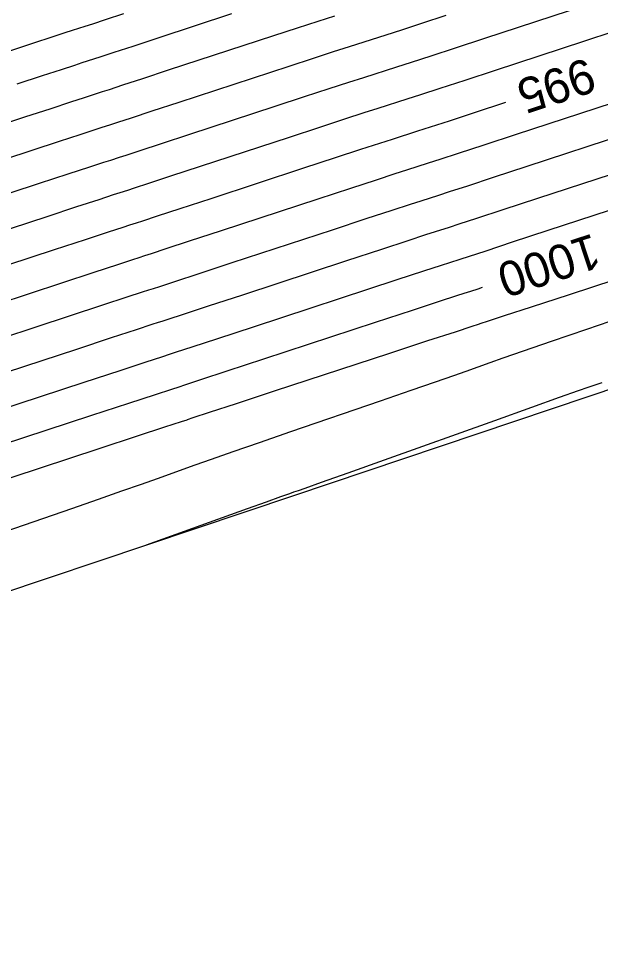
# Model space of a CAD drawing. Extents: x 2175772 to 2185556, y 721391 to 722853.
# Drawn here: x 2178934 to 2178980.9, y 721822.4 to 721896.5 of the extents above; entities that cross this region are included whole.
import ezdxf

# ---------------------------------------------------------------- set-up
doc = ezdxf.new("R2010")
doc.units = 0
for name, color, linetype in [('DT_X_Contour_Major', 7, 'Continuous'), ('DT_X_Contour_Minor', 7, 'Continuous'), ('DT_X_TIN_Hull', 7, 'Continuous')]:
    doc.layers.add(name, color=color, linetype=linetype)

msp = doc.modelspace()

# ---------------------------------------------------------------- linework, layer by layer
at = {"layer": 'DT_X_Contour_Major'}
for points in [[(2178951.175, 721896.819), (2178945.224, 721894.866), (2178943.227, 721894.21), (2178941.699, 721893.71), (2178940.64, 721893.364), (2178940.051, 721893.173), (2178939.106, 721892.87), (2178938.513, 721892.678), (2178937.446, 721892.329), (2178935.904, 721891.824), (2178933.887, 721891.162)], [(2178973.246, 721889.683), (2178970.717, 721888.854), (2178968.69, 721888.191), (2178967.167, 721887.695), (2178966.147, 721887.366), (2178964.099, 721886.711), (2178963.077, 721886.381), (2178961.546, 721885.882), (2178959.507, 721885.215), (2178956.96, 721884.38), (2178949.488, 721881.928), (2178947.011, 721881.115), (2178945.184, 721880.516), (2178944.008, 721880.131), (2178943.482, 721879.96), (2178942.946, 721879.788), (2178942.417, 721879.615), (2178941.229, 721879.227), (2178939.385, 721878.622), (2178936.883, 721877.801), (2178929.334, 721875.323)], [(2178971.364, 721874.761), (2178970.997, 721874.641), (2178970.406, 721874.448), (2178969.882, 721874.281), (2178969.289, 721874.087), (2178967.901, 721873.633), (2178965.72, 721872.918), (2178962.745, 721871.941), (2178953.752, 721868.99), (2178950.795, 721868.019), (2178948.67, 721867.322), (2178947.376, 721866.897), (2178946.913, 721866.746), (2178946.32, 721866.552), (2178945.013, 721866.124), (2178942.866, 721865.419), (2178939.879, 721864.439), (2178930.794, 721861.457)]]:
    msp.add_lwpolyline(points, dxfattribs=at)
at = {"layer": 'DT_X_Contour_Minor'}
for points in [[(2178978.356, 721897.083), (2178971.545, 721894.847), (2178969.186, 721894.074), (2178967.216, 721893.431), (2178965.635, 721892.917), (2178964.444, 721892.533), (2178961.786, 721891.683), (2178960.593, 721891.298), (2178959.005, 721890.782), (2178957.022, 721890.135), (2178954.646, 721889.356), (2178947.782, 721887.103), (2178945.497, 721886.353), (2178943.79, 721885.794), (2178942.661, 721885.424), (2178942.11, 721885.245), (2178941.41, 721885.021), (2178940.855, 721884.84), (2178939.716, 721884.468), (2178937.993, 721883.903), (2178935.684, 721883.145), (2178926.354, 721880.084)], [(2178959.473, 721896.655), (2178958.108, 721896.216), (2178956.463, 721895.682), (2178954.537, 721895.054), (2178946.076, 721892.278), (2178943.984, 721891.591), (2178942.396, 721891.071), (2178941.314, 721890.718), (2178940.737, 721890.531), (2178939.874, 721890.254), (2178939.294, 721890.066), (2178938.203, 721889.709), (2178936.6, 721889.184), (2178934.486, 721888.49), (2178928.166, 721886.416)], [(2178968.42, 721896.684), (2178966.479, 721896.05), (2178964.869, 721895.528), (2178963.592, 721895.117), (2178960.63, 721894.169), (2178959.35, 721893.757), (2178957.734, 721893.232), (2178955.78, 721892.594), (2178946.929, 721889.69), (2178944.74, 721888.972), (2178943.093, 721888.432), (2178941.988, 721888.071), (2178941.424, 721887.888), (2178940.642, 721887.637), (2178940.075, 721887.453), (2178938.96, 721887.088), (2178937.296, 721886.543), (2178935.085, 721885.818), (2178928.458, 721883.642)], [(2178942.47, 721896.83), (2178941.002, 721896.349), (2178939.967, 721896.011), (2178939.365, 721895.816), (2178938.337, 721895.487), (2178937.733, 721895.291), (2178936.69, 721894.95), (2178935.208, 721894.465), (2178933.287, 721893.835)], [(2178981.958, 721895.403), (2178979.511, 721894.6), (2178972.396, 721892.266), (2178969.952, 721891.464), (2178967.953, 721890.811), (2178966.401, 721890.306), (2178965.296, 721889.95), (2178962.943, 721889.197), (2178961.835, 721888.84), (2178960.275, 721888.332), (2178958.265, 721887.675), (2178955.803, 721886.868), (2178948.635, 721884.515), (2178946.254, 721883.734), (2178944.487, 721883.155), (2178943.335, 721882.778), (2178942.796, 721882.602), (2178942.178, 721882.404), (2178941.636, 721882.228), (2178940.473, 721881.847), (2178938.689, 721881.262), (2178936.284, 721880.473), (2178929.042, 721878.096)], [(2178981.821, 721889.636), (2178974.098, 721887.102), (2178971.483, 721886.244), (2178969.428, 721885.572), (2178967.933, 721885.084), (2178966.999, 721884.783), (2178965.256, 721884.225), (2178964.319, 721883.922), (2178962.817, 721883.433), (2178960.75, 721882.756), (2178958.117, 721881.892), (2178950.341, 721879.34), (2178947.768, 721878.496), (2178945.882, 721877.877), (2178944.682, 721877.484), (2178944.168, 721877.317), (2178943.714, 721877.171), (2178943.197, 721877.003), (2178941.986, 721876.606), (2178940.081, 721875.981), (2178937.482, 721875.128), (2178929.626, 721872.55)], [(2178982.976, 721887.154), (2178974.949, 721884.52), (2178972.248, 721883.634), (2178970.165, 721882.952), (2178968.699, 721882.474), (2178967.851, 721882.199), (2178966.412, 721881.739), (2178965.562, 721881.463), (2178964.088, 721880.983), (2178961.992, 721880.296), (2178959.274, 721879.405), (2178951.193, 721876.752), (2178948.525, 721875.877), (2178946.579, 721875.238), (2178945.355, 721874.837), (2178944.854, 721874.674), (2178944.483, 721874.555), (2178943.978, 721874.39), (2178942.743, 721873.985), (2178940.777, 721873.341), (2178938.081, 721872.456), (2178929.918, 721869.776)], [(2178984.13, 721884.672), (2178975.8, 721881.938), (2178973.014, 721881.024), (2178970.902, 721880.332), (2178969.465, 721879.863), (2178968.703, 721879.616), (2178967.569, 721879.253), (2178966.804, 721879.005), (2178965.359, 721878.533), (2178963.235, 721877.837), (2178960.431, 721876.917), (2178952.046, 721874.165), (2178949.282, 721873.258), (2178947.276, 721872.6), (2178946.029, 721872.191), (2178945.541, 721872.031), (2178945.251, 721871.938), (2178944.759, 721871.778), (2178943.499, 721871.365), (2178941.473, 721870.7), (2178938.68, 721869.783), (2178930.21, 721867.003)], [(2178985.285, 721882.189), (2178976.651, 721879.356), (2178973.78, 721878.414), (2178971.639, 721877.712), (2178969.554, 721877.032), (2178968.726, 721876.767), (2178968.046, 721876.546), (2178966.63, 721876.083), (2178964.477, 721875.377), (2178952.899, 721871.577), (2178950.038, 721870.638), (2178947.973, 721869.961), (2178946.702, 721869.544), (2178946.227, 721869.389), (2178945.539, 721869.165), (2178944.256, 721868.744), (2178942.17, 721868.06), (2178939.28, 721867.111), (2178930.502, 721864.23)], [(2178987.595, 721877.225), (2178978.353, 721874.192), (2178975.311, 721873.194), (2178973.114, 721872.473), (2178971.763, 721872.03), (2178971.258, 721871.865), (2178971.039, 721871.795), (2178970.531, 721871.629), (2178969.172, 721871.183), (2178966.962, 721870.458), (2178963.902, 721869.454), (2178954.605, 721866.402), (2178951.552, 721865.4), (2178949.367, 721864.683), (2178948.049, 721864.251), (2178947.599, 721864.103), (2178947.555, 721864.089), (2178947.1, 721863.94), (2178945.769, 721863.503), (2178943.562, 721862.778), (2178940.478, 721861.766), (2178931.086, 721858.683)], [(2178988.204, 721874.275), (2178979.765, 721871.386), (2178976.905, 721870.406), (2178974.654, 721869.631), (2178973.01, 721869.061), (2178971.976, 721868.698), (2178970.027, 721868.002), (2178969.049, 721867.657), (2178967.575, 721867.143), (2178965.606, 721866.462), (2178963.141, 721865.612), (2178955.907, 721863.123), (2178953.391, 721862.255), (2178951.268, 721861.518), (2178949.539, 721860.913), (2178948.203, 721860.439), (2178945.165, 721859.351), (2178943.88, 721858.894), (2178942.301, 721858.339), (2178940.429, 721857.687), (2178938.265, 721856.936), (2178932.101, 721854.805)], [(2178980.998, 721867.094), (2178979.866, 721866.707), (2178979.077, 721866.431), (2178977.562, 721865.893), (2178975.32, 721865.095), (2178972.35, 721864.035), (2178963.462, 721860.859), (2178960.529, 721859.811), (2178958.395, 721859.05), (2178957.062, 721858.575), (2178956.528, 721858.386), (2178956.172, 721858.263), (2178955.837, 721858.145), (2178955.1, 721857.882), (2178953.961, 721857.474), (2178952.42, 721856.922), (2178944.288, 721854.009)]]:
    msp.add_lwpolyline(points, dxfattribs=at)
at = {"layer": 'DT_X_TIN_Hull'}
msp.add_lwpolyline([(2178623.731, 721746.955), (2178647.535, 721754.586), (2178648.95, 721755.04), (2178672.703, 721762.834), (2178695.543, 721770.328), (2178719.209, 721778.379), (2178742.875, 721786.431), (2178746.708, 721787.735), (2178770.443, 721795.584), (2178794.178, 721803.433), (2178795.878, 721803.995), (2178819.557, 721812.012), (2178837.71, 721818.159), (2178861.405, 721826.129), (2178885.1, 721834.1), (2178908.796, 721842.07), (2178932.491, 721850.041), (2178956.186, 721858.011), (2178979.881, 721865.982), (2179003.576, 721873.952)], dxfattribs=at)

# ---------------------------------------------------------------- texts
at = {"layer": 'DT_X_Contour_Major'}
for s, rotation, p in [('995', 198.16726, (2178979.869, 721893.33)), ('1000', 198.16052, (2178980.27, 721879.155))]:
    msp.add_text(s, height=2.8, rotation=rotation, dxfattribs=at).set_placement(p)

doc.saveas('drawing.dxf')
